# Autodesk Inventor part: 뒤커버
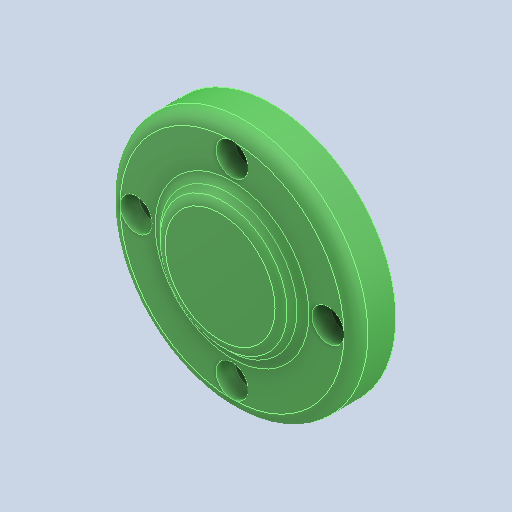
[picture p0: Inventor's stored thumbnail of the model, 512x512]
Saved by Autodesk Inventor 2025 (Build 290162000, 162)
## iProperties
Created: 2024-07
Part Number: 뒤커버
Material: 알루미늄 6061
Document SubType Name: Modeling
Designer: myung
Density: 2.71 g/cm^3
Appearance: 기본값
Author: jhkim
Sending System: Autodesk Inventor 2025
Preprocessor: ST-DEVELOPER v20
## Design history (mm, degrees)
feature "솔리드1"
node "솔리드2"
